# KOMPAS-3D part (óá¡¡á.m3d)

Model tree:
1. Эскиз:3
2. Листовое тело:2
     Расстояние 1 = 54; Расстояние 2 = 54
3. Эскиз:19
4. Сгиб по эскизу:10
     Толщина листового тела = 2; Ширина освобождения сгиба = 2; Глубина освобождения сгиба = 1; Ширина 1 = 10; Ширина 2 = 10
5. Сгиб(1) - Сгиб по эскизу:10
     Радиус сгиба = 1; Коэффициент = 0.4; Величина сгиба = 10
6. Эскиз:20
7. Сгиб по эскизу:11
     Толщина листового тела = 2; Ширина освобождения сгиба = 2; Глубина освобождения сгиба = 1; Ширина 1 = 10; Ширина 2 = 10
8. Сгиб(1) - Сгиб по эскизу:11
     Радиус сгиба = 1; Коэффициент = 0.4; Величина сгиба = 10
9. Эскиз:23
10. Операция выдавливания:3
     Расстояние 1 = 0.5; Расстояние 2 = 67
11. Эскиз:24
12. Операция выдавливания:4
     Расстояние 1 = 89; Расстояние 2 = 67
13. Эскиз:25
14. Сгиб по эскизу:14
     Толщина листового тела = 2; Ширина освобождения сгиба = 2; Глубина освобождения сгиба = 1; Ширина 1 = 10; Ширина 2 = 10
15. Сгиб(1) - Сгиб по эскизу:14
     Радиус сгиба = 1; Коэффициент = 0.4; Величина сгиба = 10
16. Эскиз:28
17. Операция выдавливания:5
     Расстояние 1 = 50.6
18. Эскиз:29
19. Сгиб по эскизу:16
     Толщина листового тела = 2; Ширина освобождения сгиба = 2; Глубина освобождения сгиба = 1; Ширина 1 = 10; Ширина 2 = 10
20. Сгиб(1) - Сгиб по эскизу:16
     Радиус сгиба = 1; Коэффициент = 0.4; Величина сгиба = 10
21. Эскиз:30
22. Сгиб по эскизу:17
     Толщина листового тела = 2; Ширина освобождения сгиба = 2; Глубина освобождения сгиба = 1; Ширина 1 = 10; Ширина 2 = 10
23. Сгиб(1) - Сгиб по эскизу:17
     Радиус сгиба = 1; Коэффициент = 0.4; Величина сгиба = 10
24. Эскиз:31
25. Сгиб по эскизу:18
     Толщина листового тела = 2; Ширина освобождения сгиба = 2; Глубина освобождения сгиба = 1; Ширина 1 = 10; Ширина 2 = 10
26. Сгиб(1) - Сгиб по эскизу:18
     Радиус сгиба = 1; Коэффициент = 0.4; Величина сгиба = 10
27. Эскиз:32
28. Вырезать элемент выдавливания:1
     Расстояние 1 = 132
29. Эскиз:33
30. Вырезать элемент выдавливания:2
     Расстояние 1 = 132
31. Эскиз:34
32. Вырезать элемент выдавливания:3
     Расстояние 1 = 16
33. Эскиз:35
34. Вырезать элемент выдавливания:4
     Расстояние 1 = 16
35. Эскиз:36
36. Вырезать элемент выдавливания:5
     Расстояние 1 = 132
37. Эскиз:37
38. Вырезать элемент выдавливания:6
     Расстояние 1 = 132
39. Эскиз:38
40. Вырезать элемент выдавливания:7
     Расстояние 1 = 132
41. Эскиз:39
42. Вырезать элемент выдавливания:8
     Расстояние 1 = 132
43. Эскиз:41
44. Вырезать элемент выдавливания:10
     Расстояние 1 = 132

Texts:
  stalker61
